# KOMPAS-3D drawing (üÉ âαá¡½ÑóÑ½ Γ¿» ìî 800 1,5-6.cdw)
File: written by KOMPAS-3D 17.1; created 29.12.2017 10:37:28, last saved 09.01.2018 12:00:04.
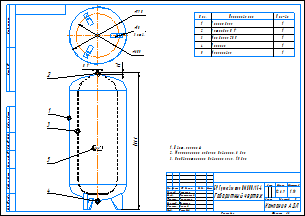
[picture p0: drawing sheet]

Sheet 1: A3, landscape, title-block layout from C:\Лощинин\GRAPHIC.LYT style 1

Title block, sheet 1: name: БР Гранлевел тип НМ 800/1,5-6 / Габаритный чертеж; mass: 126,9; sheets: 1; sheet format: A3; stored path: \\Fsk1\files\АП\20_PKO\02_Насосное направление\Разработка\04_Проекты разные\Баки\КД действующая\Баки Flexcon R\Компас\Чертежи\БР Гранлевел тип НМ 800 1,5-6.cdw; drawn by: Лощинин; checked by: Хантимеров

Views: Проекционный вид 4, Проекционный вид 5
Referenced files in K:\АП\20_PKO\02_Насосное направление\Разработка\04_Проекты разные\Баки\КД действующая\Баки Flexcon R\Компас\: 16802_Flexcon_800_1-6.m3d
Referenced files in C:\Лощинин\: GRAPHIC.LYT
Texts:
  IvAn
  ADL
  Поз.
  Кол-во
  Корпус бака
  Мембрана SBR
  Патрубок G 1"
  Ниппель
  Маркировка
  АДЛ
  Цвет: красный
  Максимальное рабочее давление: 6 бар
  Предварительное давление газа: 1,5 бар
  ACAD_ISO03W100_RGB_223_127_255_SC_0.063_THICK_0.05
  ACAD_ISO03W100_RGB_223_127_255_SC_1_THICK_0.05
  Лит-Масса-Масштаб
  Материал-Предприятие
  Масштаб
  Изм.
  Лист
  № докум.
  Подп.
  Дата
  Лит.
  Разраб.
  Пров.
  Т.контр.
  Курлыкина
  Листов
  Нач.отд.
  Щетинин
  Н.контр.
  Долгов
  Утв.
  Рашидов
  Компания АДЛ
  Изменение
  Номер документа
  Подпись
  Обозначение документа
  Наименование изделия
  Масса изделия по ГОСТ 2.109-73
  Порядковый номер листа
  Общее количество листов в документе
  Характер работы, выполненной лицом, подписавшим документ
  Наименование или индекс предприятия, выпускающего документ
  Инв. № подл.
  Подп. и дата
  Взам. инв. №
  Инв. № дубл.
  Инвентарный номер подлинника по ГОСТ 2.501-68
  Подпись принявшего подлинник в отдел технической документации
  Инвентарный номер подлинника, взамен которого выпущен данный подлинник
  Инвентарный номер дубликата по ГОСТ 2.502-68
  Подпись принявшего дубликат в отдел технической документации
  Справ. №
  Перв. примен.
  Обозначение документа, взамен или на основании которого выпущен данный документ
  Обозначение документа, в котором впервые записан данный документ
  Подпись лица, копировавшего чертеж
  Обозначение формата листа
Dimensions and other numbers on the sheet: 1; 3; 2; 4; 5; 1890; 21; 790; 605; 18; 3 отв.; 16802_Flexcon_800_1-6; 1:15; 126,9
